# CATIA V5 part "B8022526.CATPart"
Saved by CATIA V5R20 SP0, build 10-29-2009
Part number: B8022526
Revision: 7
Definition: design
Nomenclature: B8022526
Source: made
Description: NOT SPECIFIED
Bounding box of the stored display mesh (mm): x -22.5 to 22.5, y -22.5 to 22.5, z -9 to 26
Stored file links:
  C:\Users\Utente\Desktop\3D files B802\B8022526.CATPart
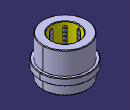
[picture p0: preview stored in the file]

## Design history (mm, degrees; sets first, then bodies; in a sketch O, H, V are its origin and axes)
Body1 "MANIFOLD_SOLID_BREP #38" (main body)
  Solid1: solid without history
Body2 "MANIFOLD_SOLID_BREP #76"
  Solid2: solid without history
Body3 "MANIFOLD_SOLID_BREP #114"
  Solid3: solid without history
Body4 "MANIFOLD_SOLID_BREP #152"
  Solid4: solid without history
Body5 "MANIFOLD_SOLID_BREP #190"
  Solid5: solid without history
Body6 "MANIFOLD_SOLID_BREP #228"
  Solid6: solid without history
Body7 "MANIFOLD_SOLID_BREP #266"
  Solid7: solid without history
Body8 "MANIFOLD_SOLID_BREP #304"
  Solid8: solid without history
Body9 "MANIFOLD_SOLID_BREP #2364"
  Solid9: solid without history
Body10 "MANIFOLD_SOLID_BREP #2402"
  Solid10: solid without history
Body11 "MANIFOLD_SOLID_BREP #2440"
  Solid11: solid without history
Body12 "MANIFOLD_SOLID_BREP #2478"
  Solid12: solid without history
Body13 "MANIFOLD_SOLID_BREP #2516"
  Solid13: solid without history
Body14 "MANIFOLD_SOLID_BREP #2554"
  Solid14: solid without history
Body15 "MANIFOLD_SOLID_BREP #2592"
  Solid15: solid without history
Body16 "MANIFOLD_SOLID_BREP #2630"
  Solid16: solid without history
Body17 "MANIFOLD_SOLID_BREP #2668"
  Solid17: solid without history
Body18 "MANIFOLD_SOLID_BREP #2706"
  Solid18: solid without history
Body19 "MANIFOLD_SOLID_BREP #2744"
  Solid19: solid without history
Body20 "MANIFOLD_SOLID_BREP #2782"
  Solid20: solid without history
Body21 "MANIFOLD_SOLID_BREP #2820"
  Solid21: solid without history
Body22 "MANIFOLD_SOLID_BREP #2858"
  Solid22: solid without history
Body23 "MANIFOLD_SOLID_BREP #2896"
  Solid23: solid without history
Body24 "MANIFOLD_SOLID_BREP #2934"
  Solid24: solid without history
Body25 "MANIFOLD_SOLID_BREP #2972"
  Solid25: solid without history
Body26 "MANIFOLD_SOLID_BREP #3010"
  Solid26: solid without history
Body27 "MANIFOLD_SOLID_BREP #3048"
  Solid27: solid without history
Body28 "MANIFOLD_SOLID_BREP #3086"
  Solid28: solid without history
Body29 "MANIFOLD_SOLID_BREP #3124"
  Solid29: solid without history
Body30 "MANIFOLD_SOLID_BREP #3162"
  Solid30: solid without history
Body31 "MANIFOLD_SOLID_BREP #3200"
  Solid31: solid without history
Body32 "MANIFOLD_SOLID_BREP #3238"
  Solid32: solid without history
Body33 "MANIFOLD_SOLID_BREP #3276"
  Solid33: solid without history
Body34 "MANIFOLD_SOLID_BREP #3314"
  Solid34: solid without history
Body35 "MANIFOLD_SOLID_BREP #3352"
  Solid35: solid without history
Body36 "MANIFOLD_SOLID_BREP #3390"
  Solid36: solid without history
Body37 "MANIFOLD_SOLID_BREP #3428"
  Solid37: solid without history
Body38 "MANIFOLD_SOLID_BREP #3466"
  Solid38: solid without history
Body39 "MANIFOLD_SOLID_BREP #3504"
  Solid39: solid without history
Body40 "MANIFOLD_SOLID_BREP #3542"
  Solid40: solid without history
Body41 "MANIFOLD_SOLID_BREP #3580"
  Solid41: solid without history
Body42 "MANIFOLD_SOLID_BREP #3618"
  Solid42: solid without history
Body43 "MANIFOLD_SOLID_BREP #3656"
  Solid43: solid without history
Body44 "MANIFOLD_SOLID_BREP #3694"
  Solid44: solid without history
Body45 "MANIFOLD_SOLID_BREP #3732"
  Solid45: solid without history
Body46 "MANIFOLD_SOLID_BREP #3770"
  Solid46: solid without history
Body47 "MANIFOLD_SOLID_BREP #3808"
  Solid47: solid without history
Body48 "MANIFOLD_SOLID_BREP #3846"
  Solid48: solid without history
Body49 "MANIFOLD_SOLID_BREP #3884"
  Solid49: solid without history
Body50 "MANIFOLD_SOLID_BREP #3922"
  Solid50: solid without history
Body51 "MANIFOLD_SOLID_BREP #3960"
  Solid51: solid without history
Body52 "MANIFOLD_SOLID_BREP #3998"
  Solid52: solid without history
Body53 "MANIFOLD_SOLID_BREP #4036"
  Solid53: solid without history
Body54 "MANIFOLD_SOLID_BREP #4074"
  Solid54: solid without history
Body55 "MANIFOLD_SOLID_BREP #4112"
  Solid55: solid without history
Body56 "MANIFOLD_SOLID_BREP #4150"
  Solid56: solid without history
Body57 "MANIFOLD_SOLID_BREP #4188"
  Solid57: solid without history
Body58 "MANIFOLD_SOLID_BREP #4226"
  Solid58: solid without history
Body59 "MANIFOLD_SOLID_BREP #4264"
  Solid59: solid without history
Body60 "MANIFOLD_SOLID_BREP #4302"
  Solid60: solid without history
Body61 "MANIFOLD_SOLID_BREP #4340"
  Solid61: solid without history
Body62 "MANIFOLD_SOLID_BREP #4378"
  Solid62: solid without history
Body63 "MANIFOLD_SOLID_BREP #4416"
  Solid63: solid without history
Body64 "MANIFOLD_SOLID_BREP #4454"
  Solid64: solid without history
Body65 "MANIFOLD_SOLID_BREP #4492"
  Solid65: solid without history
Body66 "MANIFOLD_SOLID_BREP #4530"
  Solid66: solid without history
Body67 "MANIFOLD_SOLID_BREP #4568"
  Solid67: solid without history
Body68 "MANIFOLD_SOLID_BREP #4606"
  Solid68: solid without history
Body69 "MANIFOLD_SOLID_BREP #4644"
  Solid69: solid without history
Body70 "MANIFOLD_SOLID_BREP #4682"
  Solid70: solid without history
Body71 "MANIFOLD_SOLID_BREP #4720"
  Solid71: solid without history
Body72 "MANIFOLD_SOLID_BREP #4758"
  Solid72: solid without history
Body73 "MANIFOLD_SOLID_BREP #4796"
  Solid73: solid without history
